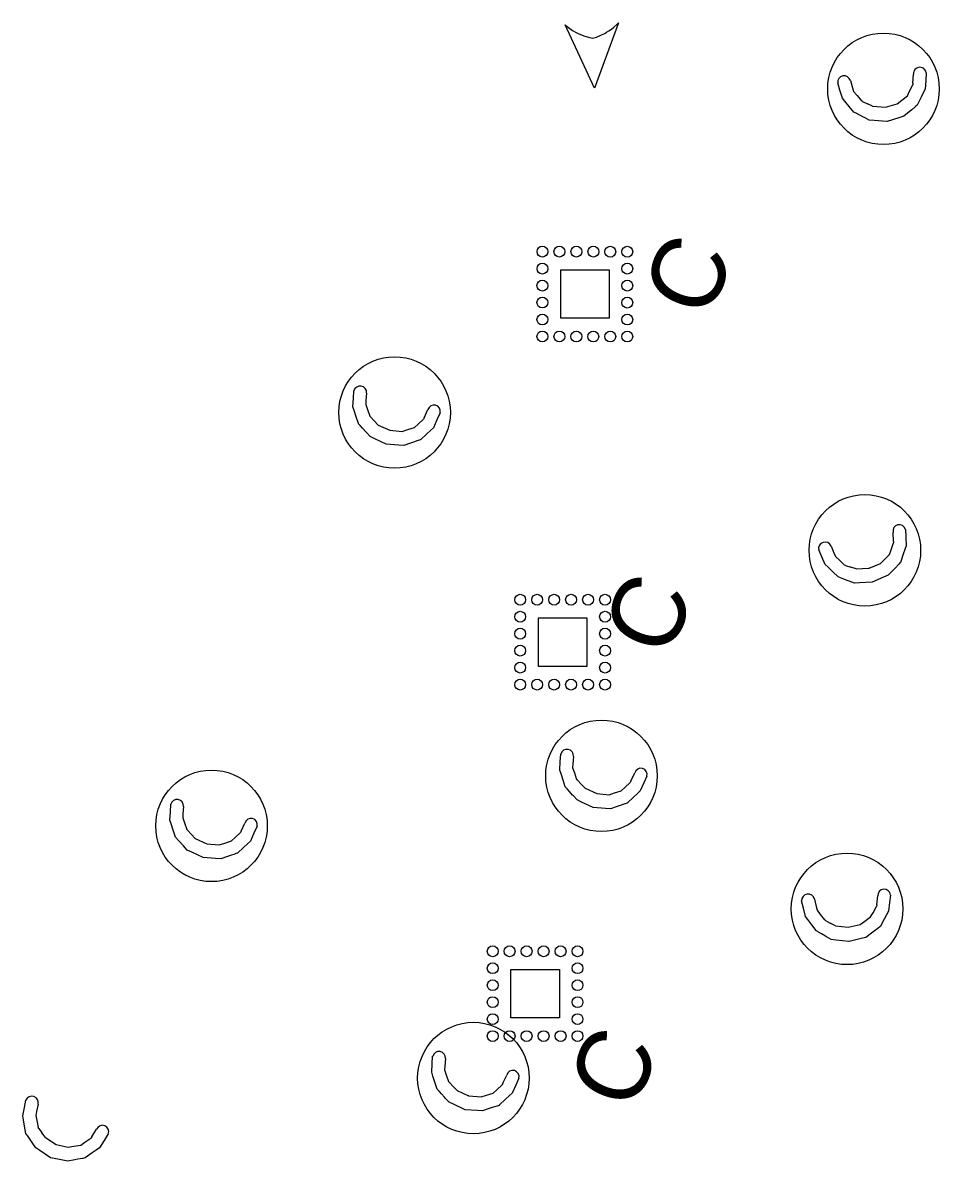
# Model space of a CAD drawing. Extents: x 2470000 to 2520000, y 340000 to 380000.
# Drawn here: x 2483382.7 to 2483571.7, y 369193.2 to 369428 of the extents above; entities that cross this region are included whole.
import ezdxf

# ---------------------------------------------------------------- set-up
doc = ezdxf.new("R2010")
doc.units = 0
for name, color, linetype in [('Coir Fiber Wattle with PAM Both CELL', 7, 'Continuous'), ('Coir Fiber Wattle with PAM Final CELL', 7, 'Continuous'), ('Prop Guardrail Anchor Unit CELL', 7, 'Continuous'), ('Rock Inlet Sediment Trap Type C CG CELL', 7, 'Continuous'), ('Rock Silt Check Type B CG CELL', 7, 'Continuous'), ('Wattle Final CELL', 7, 'Continuous')]:
    doc.layers.add(name, color=color, linetype=linetype)

# ---------------------------------------------------------------- blocks, each defined once
blk = doc.blocks.new('C2')
at = {"layer": 'Prop Guardrail Anchor Unit CELL'}
blk.add_text('C', height=0.3, dxfattribs=at).set_placement((-0.161, -0.136))

msp = doc.modelspace()

# ---------------------------------------------------------------- linework, layer by layer
at = {"layer": 'Coir Fiber Wattle with PAM Both CELL'}
for p, q in [((2483562.3, 369321.02), (2483562.23, 369322.88)), ((2483549.43, 369320.05), (2483550.04, 369318.63)), ((2483561.47, 369318.32), (2483561.82, 369319.29)), ((2483561.82, 369319.29), (2483562.32, 369320.69)), ((2483562.3, 369321.02), (2483562.32, 369320.69)), ((2483550.04, 369318.63), (2483550.36, 369317.9)), ((2483550.36, 369317.9), (2483551.16, 369317.14)), ((2483551.16, 369317.14), (2483552.21, 369316.14)), ((2483559.6, 369316.45), (2483560.45, 369317.3)), ((2483560.45, 369317.3), (2483561.47, 369318.32)), ((2483552.44, 369316.07), (2483552.21, 369316.14)), ((2483552.44, 369316.07), (2483553.49, 369315.71)), ((2483554.62, 369315.33), (2483553.49, 369315.71)), ((2483554.62, 369315.33), (2483557.24, 369315.47)), ((2483557.26, 369315.47), (2483557.24, 369315.47)), ((2483557.26, 369315.47), (2483559.6, 369316.45)), ((2483546, 369247.24), (2483546.36, 369245.73)), ((2483558.85, 369246.05), (2483558.81, 369245.72)), ((2483558.85, 369246.05), (2483559.08, 369247.9)), ((2483546.36, 369245.73), (2483546.55, 369244.96)), ((2483546.55, 369244.96), (2483547.22, 369244.08)), ((2483547.22, 369244.08), (2483548.09, 369242.92)), ((2483557.58, 369243.54), (2483558.09, 369244.43)), ((2483558.09, 369244.43), (2483558.81, 369245.72)), ((2483548.3, 369242.81), (2483548.09, 369242.92)), ((2483548.3, 369242.81), (2483549.28, 369242.28)), ((2483550.32, 369241.72), (2483549.28, 369242.28)), ((2483550.32, 369241.72), (2483552.94, 369241.42)), ((2483552.95, 369241.42), (2483552.94, 369241.42)), ((2483552.95, 369241.42), (2483555.42, 369242)), ((2483555.42, 369242), (2483556.41, 369242.7)), ((2483556.41, 369242.7), (2483557.58, 369243.54))]:
    msp.add_line(p, q, dxfattribs=at)
for points in [[(2483564.76, 369323.47), (2483564.84, 369321.91), (2483564.95, 369320.1), (2483564.67, 369319.31), (2483564.33, 369318.35), (2483563.73, 369316.66), (2483563.7, 369316.63), (2483563.4, 369316.31), (2483563.35, 369316.26), (2483562.69, 369315.57), (2483562.23, 369315.09), (2483561.21, 369314.03), (2483560.26, 369313.61), (2483557.93, 369312.58), (2483557.92, 369312.57), (2483555.28, 369312.47), (2483554.25, 369312.42), (2483553.19, 369312.82), (2483552.97, 369312.9), (2483552.07, 369313.24), (2483551.39, 369313.49), (2483551.23, 369313.55), (2483550.88, 369313.68), (2483550.87, 369313.69), (2483549.79, 369314.74), (2483548.82, 369315.67), (2483548.24, 369316.23), (2483547.53, 369317.84), (2483546.89, 369319.25)], [(2483561.67, 369248.06), (2483561.5, 369246.51), (2483561.3, 369244.71), (2483560.9, 369243.98), (2483560.41, 369243.09), (2483559.54, 369241.52), (2483559.5, 369241.5), (2483559.15, 369241.23), (2483559.09, 369241.19), (2483558.32, 369240.62), (2483557.79, 369240.22), (2483556.62, 369239.34), (2483555.61, 369239.08), (2483553.14, 369238.45), (2483553.12, 369238.45), (2483550.51, 369238.78), (2483549.49, 369238.91), (2483548.51, 369239.48), (2483548.3, 369239.6), (2483547.47, 369240.08), (2483546.83, 369240.44), (2483546.69, 369240.53), (2483546.37, 369240.71), (2483546.36, 369240.72), (2483545.47, 369241.93), (2483544.67, 369243.01), (2483544.19, 369243.67), (2483543.75, 369245.37), (2483543.36, 369246.87)]]:
    msp.add_lwpolyline(points, dxfattribs=at)
for centre in [(2483556.41, 369319.17), (2483552.73, 369245.21)]:
    msp.add_circle(centre, 11.5, dxfattribs=at)
for centre, radius, start, end in [((2483563.49, 369323.17), 1.3, 13.1143, 193.1143), ((2483548.19, 369319.55), 1.33, 22.0017, 193.1143), ((2483560.38, 369247.98), 1.3, 3.5693, 183.5693), ((2483544.69, 369246.95), 1.33, 12.4566, 183.5693)]:
    msp.add_arc(centre, radius, start, end, dxfattribs=at)
at = {"layer": 'Coir Fiber Wattle with PAM Final CELL'}
for p, q in [((2483553.42, 369416.07), (2483553.86, 369414.58)), ((2483565.63, 369413.85), (2483566.29, 369415.18)), ((2483566.32, 369415.51), (2483566.29, 369415.18)), ((2483566.32, 369415.51), (2483566.46, 369417.37)), ((2483553.86, 369414.58), (2483554.09, 369413.82)), ((2483554.09, 369413.82), (2483554.8, 369412.97)), ((2483554.8, 369412.97), (2483555.73, 369411.86)), ((2483564.04, 369412.04), (2483565.18, 369412.93)), ((2483565.18, 369412.93), (2483565.63, 369413.85)), ((2483555.94, 369411.76), (2483555.73, 369411.86)), ((2483555.94, 369411.76), (2483556.94, 369411.28)), ((2483558.01, 369410.77), (2483556.94, 369411.28)), ((2483558.01, 369410.77), (2483560.64, 369410.59)), ((2483560.65, 369410.6), (2483560.64, 369410.59)), ((2483560.65, 369410.6), (2483563.09, 369411.3)), ((2483563.09, 369411.3), (2483564.04, 369412.04)), ((2483453.52, 369350.06), (2483453.47, 369349.27)), ((2483453.64, 369351.61), (2483453.52, 369350.06)), ((2483453.47, 369349.27), (2483453.83, 369348.23)), ((2483453.83, 369348.23), (2483454.3, 369346.86)), ((2483465.5, 369346.51), (2483466.29, 369348.19)), ((2483454.46, 369346.69), (2483454.3, 369346.86)), ((2483454.46, 369346.69), (2483455.23, 369345.88)), ((2483456.05, 369345.02), (2483455.23, 369345.88)), ((2483456.05, 369345.02), (2483458.44, 369343.93)), ((2483463.51, 369344.5), (2483464.27, 369345.2)), ((2483464.27, 369345.2), (2483465.36, 369346.21)), ((2483465.5, 369346.51), (2483465.36, 369346.21)), ((2483458.45, 369343.93), (2483458.44, 369343.93)), ((2483458.45, 369343.93), (2483460.99, 369343.71)), ((2483460.99, 369343.71), (2483462.14, 369344.07)), ((2483462.14, 369344.07), (2483463.51, 369344.5)), ((2483496.3, 369276.67), (2483496.19, 369275.12)), ((2483496.19, 369275.12), (2483496.13, 369274.33)), ((2483496.13, 369274.33), (2483496.49, 369273.29)), ((2483496.49, 369273.29), (2483496.96, 369271.92)), ((2483497.12, 369271.75), (2483496.96, 369271.92)), ((2483508.16, 369271.57), (2483508.95, 369273.25)), ((2483497.12, 369271.75), (2483497.89, 369270.94)), ((2483498.71, 369270.08), (2483497.89, 369270.94)), ((2483498.71, 369270.08), (2483501.1, 369268.99)), ((2483504.8, 369269.13), (2483506.18, 369269.56)), ((2483506.18, 369269.56), (2483506.93, 369270.26)), ((2483506.93, 369270.26), (2483508.02, 369271.26)), ((2483508.16, 369271.57), (2483508.02, 369271.26)), ((2483501.12, 369268.99), (2483501.1, 369268.99)), ((2483501.12, 369268.99), (2483503.65, 369268.77)), ((2483503.65, 369268.77), (2483504.8, 369269.13)), ((2483415.9, 369266.34), (2483415.78, 369264.79)), ((2483415.78, 369264.79), (2483415.72, 369264)), ((2483415.72, 369264), (2483416.08, 369262.96)), ((2483416.08, 369262.96), (2483416.56, 369261.59)), ((2483427.75, 369261.24), (2483428.55, 369262.92)), ((2483416.72, 369261.42), (2483416.56, 369261.59)), ((2483416.72, 369261.42), (2483417.48, 369260.61)), ((2483418.31, 369259.75), (2483417.48, 369260.61)), ((2483426.53, 369259.93), (2483427.61, 369260.94)), ((2483427.75, 369261.24), (2483427.61, 369260.94)), ((2483418.31, 369259.75), (2483420.7, 369258.66)), ((2483420.71, 369258.66), (2483420.7, 369258.66)), ((2483420.71, 369258.66), (2483423.24, 369258.44)), ((2483423.24, 369258.44), (2483424.39, 369258.8)), ((2483424.39, 369258.8), (2483425.77, 369259.23)), ((2483425.77, 369259.23), (2483426.53, 369259.93)), ((2483469.89, 369214.33), (2483469.78, 369212.78)), ((2483469.78, 369212.78), (2483469.72, 369212)), ((2483469.72, 369212), (2483470.08, 369210.95)), ((2483470.08, 369210.95), (2483470.55, 369209.58)), ((2483481.75, 369209.23), (2483482.54, 369210.91)), ((2483470.71, 369209.41), (2483470.55, 369209.58)), ((2483470.71, 369209.41), (2483471.48, 369208.6)), ((2483472.3, 369207.74), (2483471.48, 369208.6)), ((2483480.52, 369207.92), (2483481.61, 369208.93)), ((2483481.75, 369209.23), (2483481.61, 369208.93)), ((2483472.3, 369207.74), (2483474.69, 369206.65)), ((2483474.71, 369206.65), (2483474.69, 369206.65)), ((2483474.71, 369206.65), (2483477.24, 369206.43)), ((2483477.24, 369206.43), (2483478.39, 369206.79)), ((2483478.39, 369206.79), (2483479.77, 369207.22)), ((2483479.77, 369207.22), (2483480.52, 369207.92))]:
    msp.add_line(p, q, dxfattribs=at)
for points in [[(2483569.04, 369417.65), (2483568.95, 369416.1), (2483568.83, 369414.28), (2483568.46, 369413.53), (2483568.02, 369412.63), (2483567.22, 369411.02), (2483567.19, 369410.99), (2483566.85, 369410.71), (2483566.79, 369410.66), (2483566.06, 369410.05), (2483565.54, 369409.63), (2483564.41, 369408.7), (2483563.42, 369408.39), (2483560.98, 369407.64), (2483560.97, 369407.64), (2483558.34, 369407.85), (2483557.31, 369407.93), (2483556.31, 369408.44), (2483556.09, 369408.55), (2483555.24, 369408.99), (2483554.59, 369409.32), (2483554.44, 369409.4), (2483554.11, 369409.57), (2483554.1, 369409.58), (2483553.15, 369410.75), (2483552.3, 369411.79), (2483551.79, 369412.42), (2483551.27, 369414.09), (2483550.81, 369415.57)], [(2483468.81, 369347.54), (2483468.16, 369346.12), (2483467.41, 369344.47), (2483466.8, 369343.9), (2483466.06, 369343.21), (2483464.75, 369341.98), (2483464.71, 369341.97), (2483464.29, 369341.83), (2483464.22, 369341.8), (2483463.31, 369341.5), (2483462.68, 369341.29), (2483461.3, 369340.82), (2483460.26, 369340.88), (2483457.71, 369341.05), (2483457.7, 369341.05), (2483455.32, 369342.18), (2483454.38, 369342.62), (2483453.63, 369343.46), (2483453.47, 369343.64), (2483452.82, 369344.35), (2483452.34, 369344.89), (2483452.22, 369345.02), (2483451.98, 369345.29), (2483451.97, 369345.3), (2483451.5, 369346.73), (2483451.08, 369348.01), (2483450.82, 369348.78), (2483450.93, 369350.53), (2483451.02, 369352.08)], [(2483511.47, 369272.6), (2483510.82, 369271.18), (2483510.07, 369269.53), (2483509.46, 369268.96), (2483508.72, 369268.27), (2483507.41, 369267.04), (2483507.37, 369267.03), (2483506.95, 369266.89), (2483506.88, 369266.86), (2483505.97, 369266.56), (2483505.34, 369266.34), (2483503.96, 369265.88), (2483502.92, 369265.94), (2483500.37, 369266.11), (2483500.36, 369266.11), (2483497.98, 369267.24), (2483497.05, 369267.68), (2483496.29, 369268.52), (2483496.13, 369268.69), (2483495.49, 369269.41), (2483495, 369269.95), (2483494.88, 369270.08), (2483494.64, 369270.35), (2483494.63, 369270.36), (2483494.16, 369271.79), (2483493.74, 369273.07), (2483493.48, 369273.84), (2483493.59, 369275.59), (2483493.68, 369277.14)], [(2483431.06, 369262.27), (2483430.42, 369260.85), (2483429.67, 369259.2), (2483429.06, 369258.63), (2483428.32, 369257.94), (2483427, 369256.72), (2483426.97, 369256.7), (2483426.55, 369256.56), (2483426.48, 369256.53), (2483425.57, 369256.23), (2483424.94, 369256.02), (2483423.55, 369255.55), (2483422.51, 369255.61), (2483419.97, 369255.78), (2483419.96, 369255.78), (2483417.57, 369256.91), (2483416.64, 369257.35), (2483415.88, 369258.19), (2483415.72, 369258.37), (2483415.08, 369259.08), (2483414.59, 369259.62), (2483414.48, 369259.75), (2483414.23, 369260.02), (2483414.23, 369260.03), (2483413.75, 369261.46), (2483413.33, 369262.74), (2483413.08, 369263.51), (2483413.18, 369265.26), (2483413.28, 369266.81)], [(2483485.06, 369210.26), (2483484.41, 369208.84), (2483483.66, 369207.19), (2483483.05, 369206.62), (2483482.31, 369205.93), (2483481, 369204.71), (2483480.96, 369204.69), (2483480.54, 369204.55), (2483480.47, 369204.52), (2483479.57, 369204.22), (2483478.94, 369204.01), (2483477.55, 369203.54), (2483476.51, 369203.6), (2483473.96, 369203.77), (2483473.95, 369203.77), (2483471.57, 369204.9), (2483470.64, 369205.34), (2483469.88, 369206.18), (2483469.72, 369206.36), (2483469.08, 369207.07), (2483468.59, 369207.61), (2483468.47, 369207.74), (2483468.23, 369208.01), (2483468.22, 369208.02), (2483467.75, 369209.46), (2483467.33, 369210.73), (2483467.07, 369211.5), (2483467.18, 369213.25), (2483467.27, 369214.8)]]:
    msp.add_lwpolyline(points, dxfattribs=at)
for centre in [(2483560.24, 369414.37), (2483459.42, 369347.6), (2483502.08, 369272.66), (2483421.67, 369262.33), (2483475.67, 369210.32)]:
    msp.add_circle(centre, 11.5, dxfattribs=at)
for centre, radius, start, end in [((2483567.75, 369417.51), 1.3, 6.3478, 186.3478), ((2483552.13, 369415.72), 1.33, 15.2351, 186.3478), ((2483452.32, 369351.74), 1.33, 354.4118, 165.5244), ((2483467.55, 369347.86), 1.3, 345.5244, 165.5244), ((2483494.98, 369276.8), 1.33, 354.4118, 165.5244), ((2483510.21, 369272.92), 1.3, 345.5244, 165.5244), ((2483414.57, 369266.47), 1.33, 354.4118, 165.5244), ((2483429.81, 369262.59), 1.3, 345.5244, 165.5244), ((2483468.57, 369214.46), 1.33, 354.4118, 165.5244), ((2483483.8, 369210.59), 1.3, 345.5244, 165.5244)]:
    msp.add_arc(centre, radius, start, end, dxfattribs=at)
at = {"layer": 'Rock Inlet Sediment Trap Type C CG CELL'}
for points in [[(2483493.67, 369367.03), (2483493.67, 369377.03), (2483503.67, 369377.03), (2483503.66, 369367.03)], [(2483489.09, 369295.24), (2483489.09, 369305.24), (2483499.09, 369305.24), (2483499.07, 369295.24)], [(2483483.42, 369222.73), (2483483.42, 369232.73), (2483493.42, 369232.73), (2483493.41, 369222.73)]]:
    msp.add_lwpolyline(points, close=True, dxfattribs=at)
for centre in [(2483489.91, 369380.78), (2483493.41, 369380.78), (2483496.91, 369380.78), (2483500.41, 369380.78), (2483503.91, 369380.77), (2483507.41, 369380.77), (2483489.91, 369377.28), (2483507.41, 369377.27), (2483489.9, 369373.78), (2483507.41, 369373.77), (2483489.9, 369370.28), (2483507.41, 369370.27), (2483489.9, 369366.78), (2483507.4, 369366.77), (2483489.9, 369363.28), (2483493.4, 369363.28), (2483496.9, 369363.27), (2483500.4, 369363.27), (2483503.9, 369363.27), (2483507.4, 369363.27), (2483485.32, 369308.98), (2483488.82, 369308.98), (2483492.32, 369308.98), (2483495.82, 369308.98), (2483499.32, 369308.98), (2483502.82, 369308.98), (2483485.32, 369305.48), (2483502.82, 369305.48), (2483485.32, 369301.98), (2483502.82, 369301.98), (2483485.32, 369298.48), (2483502.82, 369298.48), (2483485.32, 369294.98), (2483502.82, 369294.98), (2483485.32, 369291.48), (2483488.82, 369291.48), (2483492.32, 369291.48), (2483495.82, 369291.48), (2483499.32, 369291.48), (2483502.82, 369291.48), (2483479.65, 369236.47), (2483483.15, 369236.47), (2483486.65, 369236.47), (2483490.15, 369236.47), (2483493.65, 369236.47), (2483497.15, 369236.47), (2483479.65, 369232.97), (2483497.15, 369232.97), (2483479.65, 369229.47), (2483497.15, 369229.47), (2483479.65, 369225.97), (2483497.15, 369225.97), (2483479.65, 369222.47), (2483497.15, 369222.47), (2483479.65, 369218.97), (2483483.15, 369218.97), (2483486.65, 369218.97), (2483490.15, 369218.97), (2483493.65, 369218.97), (2483497.15, 369218.97)]:
    msp.add_circle(centre, 1.12, dxfattribs=at)
at = {"layer": 'Rock Silt Check Type B CG CELL'}
msp.add_lwpolyline([(2483505.6, 369427.99), (2483500.64, 369414.48), (2483494.61, 369427.54), (2483495.29, 369427.02), (2483496.1, 369426.4), (2483496.87, 369425.97), (2483497.43, 369425.71), (2483498.65, 369425.26), (2483499.42, 369425.04), (2483500.22, 369424.82), (2483501.03, 369425.05), (2483502.1, 369425.5), (2483502.78, 369425.81), (2483503.12, 369426.04), (2483503.57, 369426.31), (2483504.16, 369426.69), (2483504.63, 369427.1), (2483505.22, 369427.62)], close=True, dxfattribs=at)
at = {"layer": 'Wattle Final CELL'}
for p, q in [((2483385.92, 369204.91), (2483385.59, 369203.39)), ((2483385.59, 369203.39), (2483385.42, 369202.62)), ((2483385.42, 369202.62), (2483385.63, 369201.54)), ((2483385.63, 369201.54), (2483385.91, 369200.11)), ((2483386.05, 369199.92), (2483385.91, 369200.11)), ((2483386.05, 369199.92), (2483386.7, 369199.02)), ((2483396.96, 369198.21), (2483397.97, 369199.77)), ((2483387.39, 369198.05), (2483386.7, 369199.02)), ((2483387.39, 369198.05), (2483389.61, 369196.64)), ((2483394.71, 369196.5), (2483395.56, 369197.09)), ((2483395.56, 369197.09), (2483396.77, 369197.93)), ((2483396.96, 369198.21), (2483396.77, 369197.93)), ((2483389.62, 369196.63), (2483389.61, 369196.64)), ((2483389.62, 369196.63), (2483392.1, 369196.07)), ((2483392.1, 369196.07), (2483393.29, 369196.27)), ((2483393.29, 369196.27), (2483394.71, 369196.5))]:
    msp.add_line(p, q, dxfattribs=at)
msp.add_lwpolyline([(2483400.37, 369198.78), (2483399.54, 369197.46), (2483398.57, 369195.93), (2483397.89, 369195.45), (2483397.06, 369194.87), (2483395.59, 369193.84), (2483395.55, 369193.83), (2483395.11, 369193.75), (2483395.04, 369193.73), (2483394.1, 369193.56), (2483393.44, 369193.43), (2483392, 369193.16), (2483390.98, 369193.37), (2483388.49, 369193.89), (2483388.48, 369193.89), (2483386.27, 369195.34), (2483385.41, 369195.9), (2483384.78, 369196.84), (2483384.64, 369197.04), (2483384.1, 369197.83), (2483383.7, 369198.44), (2483383.6, 369198.58), (2483383.4, 369198.89), (2483383.39, 369198.89), (2483383.12, 369200.38), (2483382.88, 369201.7), (2483382.74, 369202.5), (2483383.08, 369204.22), (2483383.39, 369205.74)], dxfattribs=at)
for centre, radius, start in [((2483384.62, 369205.23), 1.33, 346.4504), ((2483399.17, 369199.27), 1.3, 337.5631)]:
    msp.add_arc(centre, radius, start, 157.5631, dxfattribs=at)

# ---------------------------------------------------------------- block references
at = {"layer": 'Rock Inlet Sediment Trap Type C CG CELL', "xscale": 50, "yscale": 50, "rotation": 67.56305879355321}
for p in [(2483520.86, 369376.53), (2483512.65, 369306.63), (2483505.48, 369213.08)]:
    msp.add_blockref('C2', p, dxfattribs=at)

doc.saveas('drawing.dxf')
